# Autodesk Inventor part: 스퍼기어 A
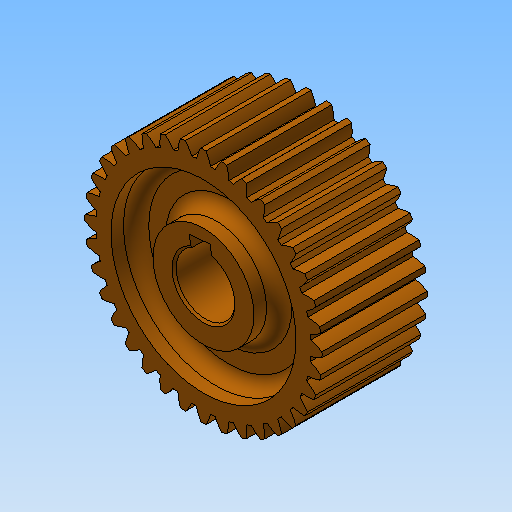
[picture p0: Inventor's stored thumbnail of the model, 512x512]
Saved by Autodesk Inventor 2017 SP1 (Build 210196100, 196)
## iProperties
Created: 2020-04
Part Number: 스퍼기어 A
Material: 강철, 연강
Document SubType Name: Modeling
Designer: mduedu
Categories: <?xml version="1.0" encoding="UTF-16"?> <MemberInstance><Categories><FamilyTemplate><FamilyTemplateParameter ValueType="xs:double" Id="1" ObjectReferenceKey="da
Density: 7.86 g/cm^3
Mass: 321.469 g
Surface Area: 147.737 cm^2
Volume: 40.8993 cm^3
Appearance: 주황색
Author: mduedu
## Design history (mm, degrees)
sketch "Sketch1"
  geometry: C1 r 28.2 at (0, 0)
  constraints: 1 centre point
  dimensions: "d0" = 56.4 diameter of C1 (= da_da)
extrude "Extrusion1" new body sketch "Sketch1" distance "d1" = 25 (= da_b); taper "d2" = 0 deg
workplane "Work Plane2"
sketch "Sketch2"
  geometry: C1 r 28.2 at (0, 0) reference; C2 r 27 at (0, 0)
  constraints: 1 centre point, 1 coincident
  dimensions: "d3" = 54 diameter of C2 (= da_dw)
feature "피치 지름" sketch "Sketch2" dims "d4" = 10, "d5" = 0
workplane "Work Plane8"
workplane "Work Plane9"
feature "스퍼 기어" dims "da_b" = 25, "da_d" = 54, "da_aw" = 45, "da_da" = 56.4, "da_df" = 51.129, "da_dw" = 54, angle "da_beta" = 0 deg, "da_lefttooth" = 0, "da_righttooth" = 0
node "작업 평면11"
sketch "스케치3"
  geometry: C1 r 12 at (0, 0); C2 r 22 at (0, 0); 1 further point
  constraints: 2 centre point, 2 coincident
  dimensions: "d49" = 24 diameter of C1; "d50" = 44 diameter of C2
extrude "돌출2" cut sketch "스케치3" distance "d51" = 6; taper "d52" = 0 deg
fillet "모깎기1" dims "d53" = 3
sketch "스케치4" dims "d17" = 0
  geometry: L1 (-3.06, 6.296)-(1.921, 6.731); L2 (1.921, 6.731)-(1.68, 9.483); L3 (1.68, 9.483)-(-3.301, 9.047); L4 (-3.301, 9.047)-(-3.06, 6.296); L5 (-3.728, 42.608)-(3.728, -42.608) reference; A1 r 7 centre (0, 0) between (-3.06, 6.296) and (1.921, 6.731); 1 further point
  constraints: 8 end point, 4 perpendicular, 2 point on circle, 1 centre point, 1 coincident
  dimensions: "d54" = 14 diameter of A1; "d63" = 16.3 dimension on A1 L3; "d64" = 5 distance of L2.end L3.end
extrude "돌출3" cut sketch "스케치4" stored distance "d58" = 6; taper "d59" = 0 deg
chamfer "모따기1" distance "d60" = 0.5; stored, may be unused: second distance "d61" = 2, angle "d62" = 45 deg
body "Solid1"
mirror "대칭1"
body "Srf1"
other parameters: "d16" = 45 (= da_aw), "d34" = 5 deg (computed from da_z), "d39" = 0, "d41" = 0, "d43" = 45 (= da_aw), "d46" = 45 (= da_aw), "d47" = 0, "d48" = 0
